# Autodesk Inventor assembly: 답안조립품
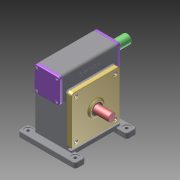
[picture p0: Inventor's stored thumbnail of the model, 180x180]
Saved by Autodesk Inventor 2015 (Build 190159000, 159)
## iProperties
Created: 2025-06
Part Number: 답안조립품
Document SubType Name: Assembly
Designer: 104
Author: 104
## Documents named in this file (13)
- C:\Users\104\Desktop\750603V1014\답안조립품.iam
- C:\Users\104\Desktop\750603V1014\가져온 구성요소\6각 구멍붙이 볼트 M8x20\6각 구멍붙이 볼트 M8x20.ipt
- C:\Users\104\Desktop\750603V1014\가져온 구성요소\깊은 홈 볼 베어링 6206\깊은 홈 볼 베어링 6206.ipt
- C:\Users\104\Desktop\750603V1014\가져온 구성요소\깊은 홈 볼 베어링 6209\깊은 홈 볼 베어링 6209.ipt
- C:\Users\104\Desktop\750603V1014\가져온 구성요소\뒷커버\뒷커버.ipt
- C:\Users\104\Desktop\750603V1014\본체.ipt
- C:\Users\104\Desktop\750603V1014\가져온 구성요소\앞커버\앞커버.ipt
- C:\Users\104\Desktop\750603V1014\가져온 구성요소\오일 실 30 42 7\오일 실 30 42 7.ipt
- C:\Users\104\Desktop\750603V1014\가져온 구성요소\오일 실 35 55 11\오일 실 35 55 11.ipt
- C:\Users\104\Desktop\750603V1014\가져온 구성요소\웜 샤프트\웜 샤프트.ipt
- C:\Users\104\Desktop\750603V1014\가져온 구성요소\웜 휠 커버\웜 휠 커버.ipt
- C:\Users\104\Desktop\750603V1014\가져온 구성요소\웜 휠\웜 휠.ipt
- C:\Users\104\Desktop\750603V1014\가져온 구성요소\6각 구멍붙이 볼트 M6x12\6각 구멍붙이 볼트 M6x12.ipt
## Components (12 placed, 2 different names)
1. 6각 구멍붙이 볼트 M8x20:1
2. 6각 구멍붙이 볼트 M8x20:2
3. 6각 구멍붙이 볼트 M8x20:3
4. 6각 구멍붙이 볼트 M8x20:4
5. 6각 구멍붙이 볼트 M6x12:2
6. 6각 구멍붙이 볼트 M6x12:3
7. 6각 구멍붙이 볼트 M6x12:4
8. 6각 구멍붙이 볼트 M6x12:5
9. 6각 구멍붙이 볼트 M6x12:1
10. 6각 구멍붙이 볼트 M6x12:6
11. 6각 구멍붙이 볼트 M6x12:7
12. 6각 구멍붙이 볼트 M6x12:8
